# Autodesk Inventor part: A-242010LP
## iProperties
Author: Administrator
Shininess: 20.0
PropertySet Name: _Private Model Information
Length Units: 11272
Angle Units: 11286
Time Units: 11279
Mass Units: 11290
Length Display Precision: 3
Angle Display Precision: 2
Compacted: True
Created: 2001-02
Part Number: A-242010LP
Document SubType Name: Sheet Metal
Designer: Administrator
Material: Default
Control State: 0
Master: False
Checked Out: False
PropertySet Name: Design Tracking Control
Density: 7.86
Volumn: 2671.380171849356
Area: 17571.460539808013
PropertySet Name: Model Information
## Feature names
1. Extrusion1
2. Extrusion2
3. Extrusion3
4. Shell1
5. Fillet1
6. Extrusion4
7. Rectangular Pattern1
8. TallBoxPattern [Rectangular Pattern]
9. WideStandoffPattern [Rectangular Pattern]
10. Extrusion5
11. Extrusion6
12. Extrusion7
13. Fillet2
14. Extrusion8
15. TallBraces [Extrusion]
